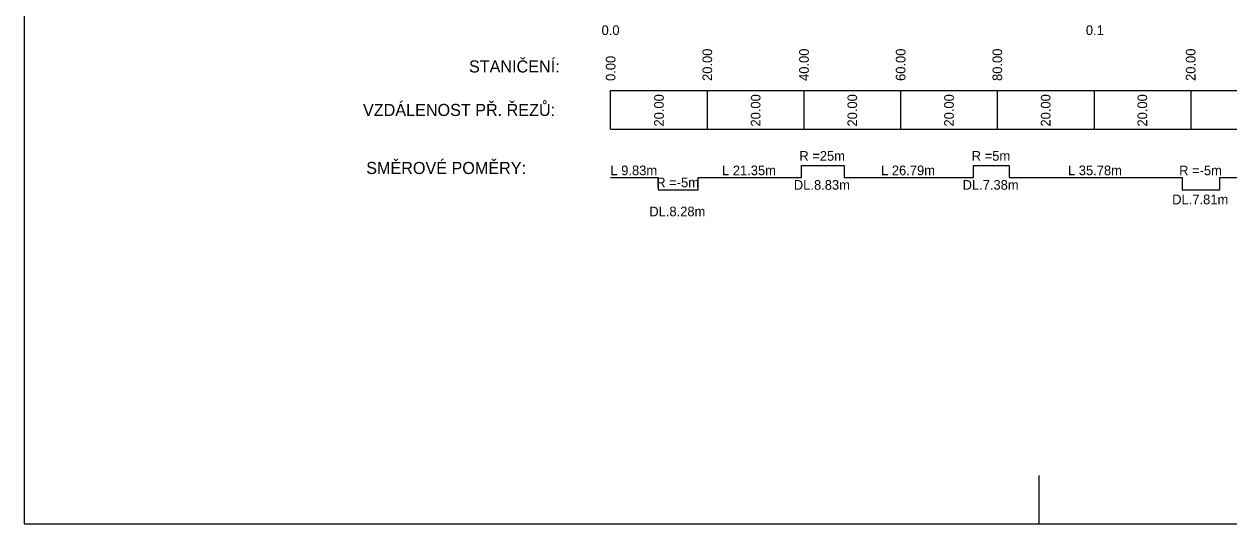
# Model space of a CAD drawing. Extents: x -559887 to -559467, y -1165800 to -1165503.
# Drawn here: x -559887.4 to -559638.1, y -1165799.7 to -1165696.3 of the extents above; entities that cross this region are included whole.
import ezdxf

# ---------------------------------------------------------------- set-up
doc = ezdxf.new("R2010")
doc.units = 0
doc.layers.add('11', color=7, linetype='Continuous')

msp = doc.modelspace()

# ---------------------------------------------------------------- linework, layer by layer
for p, q in [((-559887.38, -1165502.69), (-559887.38, -1165799.69)), ((-559766.04, -1165710.07), (-559568.03, -1165710.07)), ((-559766.04, -1165718.07), (-559766.04, -1165710.07)), ((-559746.04, -1165710.07), (-559746.04, -1165718.07)), ((-559726.04, -1165710.07), (-559726.04, -1165718.07)), ((-559706.04, -1165710.07), (-559706.04, -1165718.07)), ((-559686.04, -1165710.07), (-559686.04, -1165718.07)), ((-559666.04, -1165710.07), (-559666.04, -1165718.07)), ((-559646.04, -1165710.07), (-559646.04, -1165718.07)), ((-559766.04, -1165718.07), (-559568.03, -1165718.07)), ((-559677.38, -1165799.69), (-559677.38, -1165789.69)), ((-559887.38, -1165799.69), (-559467.38, -1165799.69))]:
    msp.add_line(p, q)
msp.add_lwpolyline([(-559766.04, -1165728.07), (-559756.21, -1165728.07), (-559756.21, -1165730.57), (-559747.93, -1165730.57), (-559747.93, -1165728.07), (-559726.58, -1165728.07), (-559726.58, -1165725.57), (-559717.75, -1165725.57), (-559717.75, -1165728.07), (-559690.96, -1165728.07), (-559690.96, -1165725.57), (-559683.58, -1165725.57), (-559683.58, -1165728.07), (-559647.8, -1165728.07), (-559647.8, -1165730.57), (-559639.99, -1165730.57), (-559639.99, -1165728.07), (-559600.88, -1165728.07)])

# ---------------------------------------------------------------- texts
for s, height, p in [('0.0', 2, (-559767.91, -1165698.57)), ('0.1', 2, (-559667.72, -1165698.57)), ('STANIČENÍ:', 2.5, (-559795.34, -1165706.32)), ('VZDÁLENOST PŘ. ŘEZŮ:', 2.5, (-559817.27, -1165715.32))]:
    msp.add_text(s, height=height).set_placement(p)
for s, p in [('20.00', (-559745.04, -1165708.07)), ('40.00', (-559725.04, -1165708.07)), ('60.00', (-559705.04, -1165708.07)), ('80.00', (-559685.04, -1165708.07)), ('20.00', (-559645.04, -1165708.07)), ('0.00', (-559765.04, -1165708.07)), ('20.00', (-559755.04, -1165717.5)), ('20.00', (-559735.04, -1165717.5)), ('20.00', (-559715.04, -1165717.5)), ('20.00', (-559695.04, -1165717.5)), ('20.00', (-559675.04, -1165717.5)), ('20.00', (-559655.04, -1165717.5))]:
    msp.add_text(s, height=2, rotation=90).set_placement(p)
at = {"layer": '11'}
for s, height, p in [('R =25m', 2, (-559727, -1165724.57)), ('R =5m', 2, (-559691.33, -1165724.57)), (' SMĚROVÉ POMĚRY: ', 2.5, (-559817.53, -1165727.32)), ('L 9.83m', 2, (-559766.08, -1165727.57)), ('L 21.35m', 2, (-559742.99, -1165727.57)), ('L 26.79m', 2, (-559710.09, -1165727.57)), ('L 35.78m', 2, (-559671.42, -1165727.57)), ('R =-5m', 2, (-559648.43, -1165727.58)), ('R =-5m', 2, (-559756.6, -1165730.07)), ('DL.8.83m', 2, (-559728.13, -1165730.57)), ('DL.7.38m', 2, (-559693.23, -1165730.57)), ('DL.7.81m', 2, (-559649.86, -1165733.58)), ('DL.8.28m', 2, (-559758.04, -1165736.07))]:
    msp.add_text(s, height=height, dxfattribs=at).set_placement(p)

doc.saveas('drawing.dxf')
